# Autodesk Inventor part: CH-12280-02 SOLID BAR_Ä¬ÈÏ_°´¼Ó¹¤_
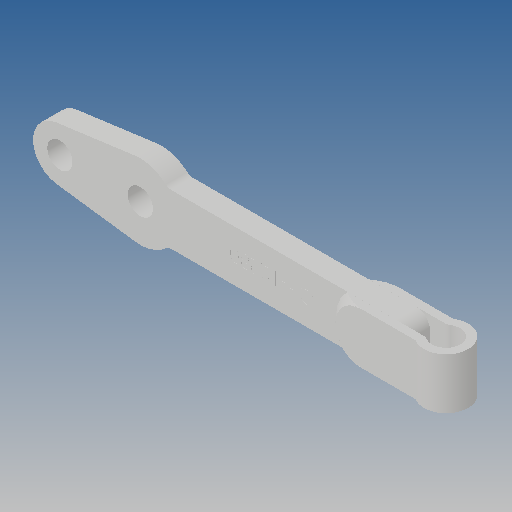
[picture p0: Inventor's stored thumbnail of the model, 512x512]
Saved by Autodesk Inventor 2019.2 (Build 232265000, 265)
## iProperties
Created: 2012-09
Part Number: CH-12280-02 SOLID BAR_Ä¬ÈÏ_°´¼Ó¹¤_
Material: Ogólny
Document SubType Name: Modeling
Designer: CADENGINEERING4
Density: 1 g/cm^3
Appearance: Domyślna
Author: CADENGINEERING4
Revision Number: ÈÎºÎ
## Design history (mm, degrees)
feature "NONE" [ÊäÈë]
feature "ÊäÈë2"
feature "ÊäÈë3"
feature "ÊäÈë4"
node "Bryła1"
node "Bryła2"
node "Bryła3"
node "Bryła4"
